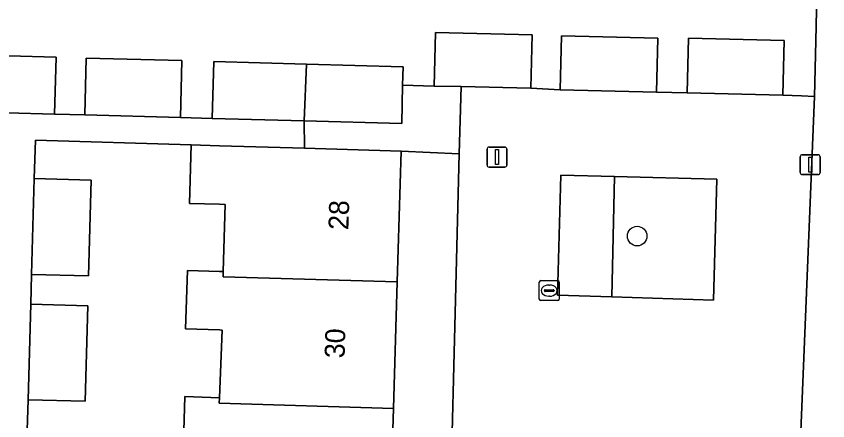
# Model space of a CAD drawing. Extents: x 162082 to 163401, y 388089 to 388636.
# Drawn here: x 162489.83 to 162530.44, y 388275.12 to 388295.36 of the extents above; entities that cross this region are included whole.
import ezdxf

# ---------------------------------------------------------------- set-up
doc = ezdxf.new("R2010")
doc.units = 0
for name, color, linetype in [('IMGEO_Boom', 7, 'Continuous'), ('IMGEO_Erf', 7, 'Continuous'), ('IMGEO_Groenvoorziening', 7, 'Continuous'), ('IMGEO_Lichtmast', 7, 'Continuous'), ('IMGEO_Muur', 7, 'Continuous'), ('IMGEO_Pand', 7, 'Continuous'), ('IMGEO_Pand_nummerreeks', 7, 'Continuous'), ('IMGEO_Rioolput', 7, 'Continuous'), ('IMGEO_Voetpad_open', 7, 'Continuous')]:
    doc.layers.add(name, color=color, linetype=linetype)

msp = doc.modelspace()

# ---------------------------------------------------------------- linework, layer by layer
at = {"layer": 'IMGEO_Boom'}
msp.add_circle((162520.903, 388284.357), 0.489, dxfattribs=at)
at = {"layer": 'IMGEO_Erf'}
for points in [[(162487.039, 388293.437), (162491.822, 388293.307), (162491.745, 388290.458), (162493.256, 388290.416), (162493.333, 388293.265), (162498.123, 388293.135), (162498.045, 388290.286), (162499.641, 388290.242), (162499.719, 388293.091), (162504.358, 388292.964), (162509.186, 388292.832), (162509.164, 388291.906), (162510.74, 388291.866), (162510.804, 388294.545), (162515.643, 388294.429), (162515.579, 388291.75), (162517.056, 388291.669), (162517.121, 388294.381), (162521.929, 388294.265), (162521.864, 388291.553), (162523.412, 388291.53), (162523.477, 388294.254), (162528.259, 388294.139), (162528.194, 388291.415), (162529.129, 388291.369), (162529.771, 388291.337), (162529.848, 388294.123), (162529.966, 388299.491)], [(162498.177, 388273.478), (162498.263, 388276.325), (162500, 388276.273), (162500.134, 388279.655), (162500, 388279.66), (162498.304, 388279.71), (162498.392, 388282.637), (162500, 388282.59), (162500.185, 388282.584), (162500.285, 388285.943), (162500, 388285.952), (162498.5, 388285.996), (162498.587, 388288.92), (162490.785, 388289.152), (162490.732, 388287.234), (162493.581, 388287.156), (162493.448, 388282.364), (162490.599, 388282.442), (162490.558, 388280.955), (162493.407, 388280.876), (162493.275, 388276.091), (162490.426, 388276.17), (162490.384, 388274.646)], [(162511.384, 388263.919), (162511.996, 388288.477), (162509.089, 388288.606), (162508.893, 388282.062), (162508.704, 388275.732), (162508.514, 388269.402)]]:
    msp.add_lwpolyline(points, dxfattribs=at)
at = {"layer": 'IMGEO_Groenvoorziening'}
for points in [[(162519.774, 388287.338), (162517.075, 388287.412), (162516.908, 388281.404), (162519.628, 388281.315)], [(162524.886, 388287.199), (162519.774, 388287.338), (162519.628, 388281.315), (162524.715, 388281.15)]]:
    msp.add_lwpolyline(points, close=True, dxfattribs=at)
at = {"layer": 'IMGEO_Lichtmast'}
for p, q in [((162513.392, 388287.908), (162513.392, 388288.708)), ((162513.392, 388288.708), (162513.392, 388287.908)), ((162513.492, 388288.808), (162514.282, 388288.808)), ((162514.282, 388288.808), (162513.492, 388288.808)), ((162514.382, 388288.708), (162514.382, 388287.908)), ((162514.382, 388287.908), (162514.382, 388288.708)), ((162529.066, 388287.531), (162529.066, 388288.331)), ((162529.066, 388288.331), (162529.066, 388287.531)), ((162529.166, 388288.431), (162529.956, 388288.431)), ((162529.956, 388288.431), (162529.166, 388288.431)), ((162530.056, 388288.331), (162530.056, 388287.531)), ((162530.056, 388287.531), (162530.056, 388288.331)), ((162514.282, 388287.808), (162513.492, 388287.808)), ((162513.492, 388287.808), (162514.282, 388287.808)), ((162529.956, 388287.431), (162529.166, 388287.431)), ((162529.166, 388287.431), (162529.956, 388287.431))]:
    msp.add_line(p, q, dxfattribs=at)
for points in [[(162513.812, 388288.683), (162513.962, 388288.683), (162513.962, 388287.933), (162513.812, 388287.933), (162513.812, 388288.683)], [(162529.486, 388288.306), (162529.636, 388288.306), (162529.636, 388287.556), (162529.486, 388287.556), (162529.486, 388288.306)]]:
    msp.add_lwpolyline(points, dxfattribs=at)
for centre, start, end in [((162513.492, 388288.708), 90, 180), ((162513.492, 388288.708), 90, 180), ((162514.282, 388288.708), 0, 90), ((162514.282, 388288.708), 360, 90), ((162529.166, 388288.331), 90, 180), ((162529.166, 388288.331), 90, 180), ((162529.956, 388288.331), 0, 90), ((162529.956, 388288.331), 360, 90), ((162513.492, 388287.908), 180, 270), ((162513.492, 388287.908), 180, 270), ((162514.282, 388287.908), 270, 0), ((162514.282, 388287.908), 270, 0), ((162529.166, 388287.531), 180, 270), ((162529.166, 388287.531), 180, 270), ((162529.956, 388287.531), 270, 0), ((162529.956, 388287.531), 270, 0)]:
    msp.add_arc(centre, 0.1, start, end, dxfattribs=at)
at = {"layer": 'IMGEO_Muur'}
msp.add_lwpolyline([(162529.966, 388299.491), (162529.848, 388294.123)], dxfattribs=at)
at = {"layer": 'IMGEO_Pand'}
for points in [[(162515.643, 388294.429), (162510.804, 388294.545), (162510.74, 388291.866), (162512.091, 388291.834), (162515.579, 388291.75)], [(162517.121, 388294.381), (162517.056, 388291.669), (162521.864, 388291.553), (162521.929, 388294.265)], [(162523.477, 388294.254), (162523.412, 388291.53), (162528.194, 388291.415), (162528.259, 388294.139)], [(162486.962, 388290.588), (162491.745, 388290.458), (162491.822, 388293.307), (162487.039, 388293.437)], [(162493.256, 388290.416), (162498.045, 388290.286), (162498.123, 388293.135), (162493.333, 388293.265)], [(162504.358, 388292.964), (162499.719, 388293.091), (162499.641, 388290.242), (162504.242, 388290.116)], [(162509.164, 388291.906), (162509.186, 388292.832), (162504.358, 388292.964), (162504.242, 388290.116), (162509.118, 388289.983)], [(162508.893, 388282.062), (162509.089, 388288.606), (162504.248, 388288.751), (162500, 388288.878), (162498.587, 388288.92), (162498.5, 388285.996), (162500, 388285.952), (162500.285, 388285.943), (162500.185, 388282.584), (162500.177, 388282.322)], [(162490.732, 388287.234), (162490.599, 388282.442), (162493.448, 388282.364), (162493.581, 388287.156)], [(162508.893, 388282.062), (162500.177, 388282.322), (162500.185, 388282.584), (162500, 388282.59), (162498.392, 388282.637), (162498.304, 388279.71), (162500, 388279.66), (162500.134, 388279.655), (162500, 388276.273), (162499.989, 388275.993), (162508.704, 388275.732)], [(162490.558, 388280.955), (162490.426, 388276.17), (162493.275, 388276.091), (162493.407, 388280.876)], [(162508.514, 388269.402), (162508.704, 388275.732), (162499.989, 388275.993), (162500, 388276.273), (162498.263, 388276.325), (162498.177, 388273.478), (162499.962, 388273.424), (162499.859, 388269.965), (162499.85, 388269.66), (162500, 388269.656)]]:
    msp.add_lwpolyline(points, close=True, dxfattribs=at)
at = {"layer": 'IMGEO_Rioolput'}
for p, q in [((162516.076, 388282.13), (162516.928, 388282.13)), ((162516.001, 388281.204), (162516.001, 388282.056)), ((162516.489, 388281.91), (162516.514, 388281.91)), ((162517.002, 388282.056), (162517.002, 388281.204)), ((162516.26, 388281.624), (162516.26, 388281.636)), ((162516.698, 388281.587), (162516.3, 388281.587)), ((162516.303, 388281.673), (162516.701, 388281.673)), ((162516.512, 388281.35), (162516.487, 388281.35)), ((162516.744, 388281.636), (162516.744, 388281.624)), ((162516.928, 388281.13), (162516.076, 388281.13))]:
    msp.add_line(p, q, dxfattribs=at)
for points in [[(162516.076, 388282.13), (162516.928, 388282.13)], [(162516.001, 388281.204), (162516.001, 388282.056)], [(162517.002, 388282.056), (162517.002, 388281.204)], [(162516.928, 388281.13), (162516.076, 388281.13)]]:
    msp.add_lwpolyline(points, dxfattribs=at)
for centre, radius, start, end in [((162516.078, 388282.054), 0.0765, 91.552, 178.448), ((162516.078, 388282.054), 0.0765, 91.552, 178.448), ((162516.926, 388282.054), 0.0765, 1.552, 88.448), ((162516.926, 388282.054), 0.0765, 1.552, 88.448), ((162516.3, 388281.633), 0.0403, 85.8775, 175.7526), ((162516.297, 388281.623), 0.0366, 178.938, 274.7102), ((162516.701, 388281.63), 0.043, 264.8664, 352.4533), ((162516.705, 388281.635), 0.0386, 1.7309, 96.639), ((162516.078, 388281.206), 0.0765, 181.552, 268.448), ((162516.078, 388281.206), 0.0765, 181.552, 268.448), ((162516.926, 388281.206), 0.0765, 271.552, 358.448), ((162516.926, 388281.206), 0.0765, 271.552, 358.448)]:
    msp.add_arc(centre, radius, start, end, dxfattribs=at)
for centre, major_axis, ratio, start_param, end_param in [((162516.488, 388281.63), (-0.387, 0.002), 0.722429, 4.712389, 7.853982), ((162516.513, 388281.63), (-0.39, 0.002), 0.717154, 1.570796, 4.712389)]:
    msp.add_ellipse(centre, major_axis=major_axis, ratio=ratio, start_param=start_param, end_param=end_param, dxfattribs=at)
at = {"layer": 'IMGEO_Voetpad_open'}
for points in [[(162532.089, 388287.917), (162533.199, 388287.922), (162533.234, 388289.327), (162533.238, 388289.496), (162533.487, 388299.428), (162533.741, 388308.189), (162533.867, 388312.548), (162530.329, 388312.664), (162530.241, 388310.204), (162530.19, 388308.231), (162529.966, 388299.491), (162529.848, 388294.123), (162529.771, 388291.337), (162528.873, 388269.279), (162528.684, 388263.269), (162528.43, 388263.268), (162528.15, 388250.86), (162531.036, 388250.765)], [(162512.091, 388291.834), (162510.74, 388291.866), (162509.164, 388291.906), (162509.118, 388289.983), (162504.242, 388290.116), (162504.248, 388288.751), (162509.089, 388288.606), (162511.996, 388288.477)], [(162529.771, 388291.337), (162529.129, 388291.369), (162528.194, 388291.415), (162523.412, 388291.53), (162521.864, 388291.553), (162517.056, 388291.669), (162515.579, 388291.75), (162512.091, 388291.834), (162511.996, 388288.477), (162511.384, 388263.919), (162511.376, 388263.608), (162513.413, 388263.567), (162517.642, 388263.483), (162520.756, 388263.421), (162520.89, 388269.524), (162524.47, 388269.414), (162528.58, 388269.288), (162528.873, 388269.279)], [(162516.908, 388281.404), (162517.075, 388287.412), (162519.774, 388287.338), (162524.886, 388287.199), (162524.715, 388281.15), (162519.628, 388281.315)]]:
    msp.add_lwpolyline(points, close=True, dxfattribs=at)
msp.add_lwpolyline([(162490.384, 388274.646), (162490.426, 388276.17), (162490.558, 388280.955), (162490.599, 388282.442), (162490.732, 388287.234), (162490.785, 388289.152), (162498.587, 388288.92), (162500, 388288.878), (162504.248, 388288.751), (162504.242, 388290.116), (162499.641, 388290.242), (162498.045, 388290.286), (162493.256, 388290.416), (162491.745, 388290.458), (162486.962, 388290.588)], dxfattribs=at)

# ---------------------------------------------------------------- texts
at = {"layer": 'IMGEO_Pand_nummerreeks'}
for s, p in [('28', (162506.45, 388284.65)), ('30', (162506.258, 388278.236))]:
    msp.add_text(s, height=1, rotation=88.2856, dxfattribs=at).set_placement(p)

doc.saveas('drawing.dxf')
